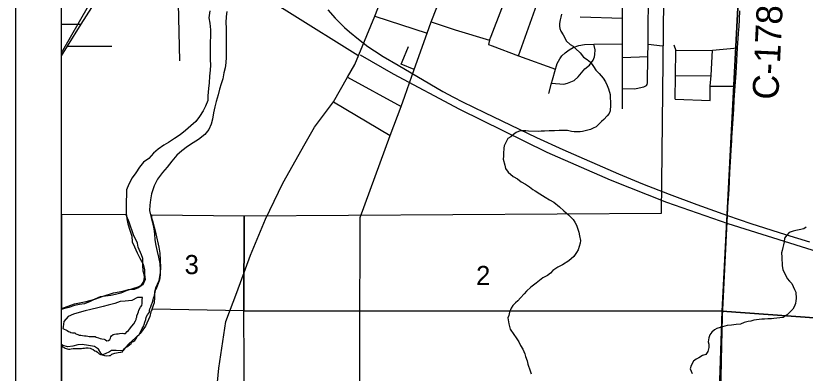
# Model space of a CAD drawing. Extents: x 0 to 34, y 0 to 22.
# Drawn here: x 23.417 to 25.144, y 18.836 to 19.618 of the extents above; entities that cross this region are included whole.
import ezdxf

# ---------------------------------------------------------------- set-up
doc = ezdxf.new("R2010")
doc.units = 0
for name, color, linetype in [('GM_X_City_Street', 7, 'Continuous'), ('GM_X_County_Road', 7, 'Continuous'), ('GM_X_County_Road_Text', 7, 'Continuous'), ('GM_X_Major_River', 7, 'Continuous'), ('GM_X_Minor_River', 7, 'Continuous'), ('GM_X_Rail_Line', 7, 'Continuous'), ('GM_X_Section', 7, 'Continuous'), ('GM_X_Section_Text', 7, 'Continuous'), ('GM_X_Township_Road', 7, 'Continuous'), ('SH_Data', 7, 'Continuous')]:
    doc.layers.add(name, color=color, linetype=linetype)

msp = doc.modelspace()

# ---------------------------------------------------------------- linework, layer by layer
at = {"layer": 'GM_X_City_Street'}
for p, q in [((24.2023, 19.6172), (24.3168, 19.5803)), ((24.652, 19.6161), (24.7447, 19.6129)), ((23.5167, 19.5995), (23.5601, 19.5999)), ((24.4535, 19.5645), (24.4571, 19.5738)), ((23.5301, 19.5518), (23.627, 19.5518)), ((24.8003, 19.5559), (24.832, 19.5522)), ((24.5165, 19.5304), (24.5976, 19.501)), ((24.7446, 19.5266), (24.8, 19.5289)), ((24.1428, 19.4837), (24.2597, 19.4199)), ((24.112, 19.4297), (24.2362, 19.356))]:
    msp.add_line(p, q, dxfattribs=at)
for points in [[(23.9629, 19.1735), (24.0008, 19.2519), (24.0497, 19.3384), (24.0703, 19.3742), (24.112, 19.4297), (24.1428, 19.4837), (24.1587, 19.5115), (24.2023, 19.6172), (24.2092, 19.6341), (24.2339, 19.694), (24.2396, 19.7104), (24.2604, 19.7707), (24.2761, 19.816), (24.2847, 19.8408), (24.2883, 19.8565), (24.2919, 19.8721), (24.2931, 19.8774), (24.3064, 19.9349), (24.3072, 19.9386), (24.3221, 20.0342)], [(24.4571, 19.5738), (24.4804, 19.634), (24.4886, 19.6556), (24.5076, 19.7055), (24.5315, 19.7681), (24.5544, 19.8322), (24.5557, 19.8359), (24.5616, 19.8511), (24.5667, 19.8645), (24.5929, 19.9328)], [(24.7446, 19.4144), (24.7446, 19.4593), (24.7446, 19.5266), (24.7446, 19.557), (24.7445, 19.5967), (24.7447, 19.6129), (24.7452, 19.6848), (24.7455, 19.7113), (24.7457, 19.7375), (24.7462, 19.8063), (24.7462, 19.8086), (24.7615, 19.8472), (24.7705, 19.8699)], [(24.7446, 19.4593), (24.7713, 19.4585), (24.7875, 19.4618), (24.7908, 19.4629), (24.7967, 19.4657), (24.7986, 19.4681), (24.7994, 19.4715), (24.8, 19.5289), (24.8003, 19.5559), (24.8016, 19.6863), (24.802, 19.7187), (24.8027, 19.7879)], [(23.7757, 19.5194), (23.772, 19.6772), (23.7732, 19.7486)], [(24.5832, 19.4484), (24.5892, 19.4709), (24.5911, 19.478), (24.5976, 19.501), (24.5998, 19.5085), (24.6012, 19.5138), (24.607, 19.5238), (24.612, 19.5302), (24.6186, 19.5369), (24.6277, 19.5439), (24.6368, 19.5489), (24.6491, 19.5533), (24.661, 19.5554), (24.6819, 19.5558), (24.7446, 19.557)], [(24.2886, 19.5005), (24.2601, 19.5124), (24.262, 19.517), (24.2763, 19.5511)], [(24.5892, 19.4709), (24.6157, 19.4683), (24.624, 19.4709), (24.6384, 19.4762), (24.6475, 19.4844), (24.6619, 19.5019), (24.672, 19.5097), (24.68, 19.5209), (24.683, 19.5282), (24.6841, 19.5337), (24.6847, 19.5439), (24.6819, 19.5558)]]:
    msp.add_lwpolyline(points, dxfattribs=at)
at = {"layer": 'GM_X_County_Road'}
for p, q in [((24.9977, 19.5686), (24.9984, 19.5788)), ((24.9984, 19.5788), (24.9991, 19.5889)), ((24.9962, 19.5483), (24.997, 19.5585)), ((24.997, 19.5585), (24.9977, 19.5686)), ((24.4594, 19.5522), (24.5165, 19.5304)), ((24.9889, 19.4334), (24.9901, 19.4539)), ((24.9901, 19.4539), (24.9907, 19.4642)), ((24.9877, 19.4129), (24.9889, 19.4334)), ((24.9762, 19.2176), (24.9775, 19.2384))]:
    msp.add_line(p, q, dxfattribs=at)
for points in [[(24.5165, 19.5304), (24.5535, 19.6327), (24.5928, 19.7413), (24.627, 19.8356)], [(24.3256, 19.6051), (24.3523, 19.6717), (24.3553, 19.6792), (24.3743, 19.7264), (24.3832, 19.7487), (24.3849, 19.753), (24.3867, 19.7574), (24.3893, 19.7639)], [(23.5167, 19.5304), (23.5301, 19.5518), (23.5601, 19.5999), (23.5828, 19.6362), (23.5847, 19.6392), (23.6379, 19.6701), (23.6483, 19.6761), (23.7173, 19.7161), (23.7665, 19.7447)], [(24.9991, 19.5889), (24.9994, 19.593), (25.0013, 19.6291)], [(24.1701, 19.1767), (24.2362, 19.356), (24.2597, 19.4199), (24.2678, 19.4419), (24.2886, 19.5005), (24.3168, 19.5803), (24.3256, 19.6051)], [(24.3256, 19.6051), (24.3781, 19.5873), (24.4535, 19.5645), (24.4508, 19.5555), (24.4594, 19.5522)], [(24.9907, 19.4642), (24.9931, 19.4925), (24.9962, 19.5483)], [(24.9851, 19.3717), (24.9865, 19.3924), (24.9877, 19.4129)], [(24.9839, 19.3514), (24.9844, 19.3623), (24.9851, 19.3717)], [(24.9814, 19.3099), (24.9824, 19.3251), (24.9835, 19.3445), (24.9839, 19.3514)], [(24.9775, 19.2384), (24.9792, 19.2756), (24.9814, 19.3099)], [(24.9749, 19.1969), (24.9751, 19.2009), (24.9762, 19.2176)], [(24.9527, 18.4155), (24.9614, 18.8646), (24.963, 18.9602), (24.9739, 19.182), (24.9749, 19.1969)], [(23.7182, 18.4291), (23.7274, 18.4574), (23.7597, 18.5372), (23.7834, 18.6002), (23.8012, 18.6519), (23.8134, 18.6813), (23.8345, 18.7159), (23.8441, 18.7268), (23.8496, 18.7388), (23.8517, 18.7479), (23.8613, 18.8473), (23.8762, 18.9492), (23.9004, 19.0127), (23.9305, 19.0946), (23.9629, 19.1735)]]:
    msp.add_lwpolyline(points, dxfattribs=at)
at = {"layer": 'GM_X_Major_River'}
for points in [[(23.8413, 19.6292), (23.8388, 19.6137), (23.8413, 19.6019), (23.8431, 19.5871), (23.8429, 19.573), (23.842, 19.5609), (23.8419, 19.5488), (23.8421, 19.5362), (23.8423, 19.5226), (23.8426, 19.5104), (23.8417, 19.4994), (23.8408, 19.4858), (23.8395, 19.4713), (23.8382, 19.4592), (23.8373, 19.4433), (23.8368, 19.4327), (23.8321, 19.4206), (23.827, 19.41), (23.8185, 19.3979), (23.8108, 19.387), (23.7997, 19.3773), (23.7882, 19.3671), (23.7763, 19.3574), (23.7641, 19.3495), (23.7511, 19.3409), (23.7404, 19.335), (23.7286, 19.3264), (23.7179, 19.3174), (23.7075, 19.3061), (23.6964, 19.2975), (23.6872, 19.2866), (23.6794, 19.2745), (23.6713, 19.2636), (23.664, 19.2496), (23.6593, 19.2372), (23.6588, 19.2246), (23.6579, 19.214), (23.6581, 19.2003), (23.6583, 19.1863)], [(23.8784, 19.6277), (23.8772, 19.6163), (23.8766, 19.6023), (23.8769, 19.5917), (23.8767, 19.5795), (23.8772, 19.5537), (23.8769, 19.5279), (23.876, 19.5154), (23.8747, 19.504), (23.8723, 19.493), (23.8699, 19.4805), (23.866, 19.4695), (23.8628, 19.4578), (23.8593, 19.4449), (23.8553, 19.4306), (23.8525, 19.4188), (23.8497, 19.4056), (23.8469, 19.3919), (23.8445, 19.3813), (23.8391, 19.3696), (23.8302, 19.3583), (23.8168, 19.3475), (23.805, 19.34), (23.7924, 19.3318), (23.7801, 19.3228), (23.7694, 19.3134), (23.7579, 19.3003), (23.7479, 19.2871), (23.7379, 19.275), (23.7267, 19.2604), (23.7193, 19.246), (23.7138, 19.2286), (23.7114, 19.2157), (23.7097, 19.2036), (23.7092, 19.1922), (23.7128, 19.1766), (23.7161, 19.1659), (23.719, 19.1522), (23.72, 19.1412), (23.721, 19.1283), (23.7231, 19.1154), (23.7264, 19.1021), (23.7293, 19.0903), (23.7318, 19.0762), (23.7324, 19.0621), (23.7327, 19.0515), (23.731, 19.0405), (23.7263, 19.0269), (23.7232, 19.019)], [(23.6583, 19.1863), (23.6597, 19.1741), (23.6622, 19.1631), (23.6666, 19.149), (23.6706, 19.1357), (23.6716, 19.1239), (23.6768, 19.1125), (23.682, 19.0995), (23.6879, 19.0877), (23.6954, 19.0747), (23.6983, 19.0625), (23.6985, 19.0519), (23.6995, 19.0409), (23.6945, 19.0295), (23.6838, 19.0243), (23.672, 19.0207), (23.6583, 19.0166), (23.6465, 19.0111), (23.6351, 19.0081), (23.6244, 19.0064), (23.613, 19.0046), (23.6016, 19.0032), (23.5898, 18.998), (23.5791, 18.9932), (23.5673, 18.988), (23.5563, 18.9862), (23.5453, 18.984), (23.5331, 18.98), (23.5209, 18.9767), (23.5167, 18.9758)], [(23.5167, 18.8959), (23.5196, 18.8937), (23.5222, 18.8921), (23.5249, 18.8913), (23.5294, 18.8893), (23.532, 18.8889), (23.5347, 18.8889), (23.5377, 18.8896), (23.5422, 18.8902), (23.5449, 18.8905), (23.5476, 18.8905), (23.557, 18.8903), (23.5604, 18.8906), (23.5635, 18.8913), (23.5669, 18.8909), (23.5703, 18.8919), (23.5748, 18.8918), (23.5794, 18.891), (23.5827, 18.8898), (23.5857, 18.8882), (23.5899, 18.8855), (23.5925, 18.8843), (23.5955, 18.882), (23.5992, 18.8788), (23.6022, 18.8769), (23.6059, 18.8761), (23.6108, 18.8752), (23.6146, 18.874), (23.621, 18.8746), (23.6241, 18.8753), (23.6268, 18.8775), (23.631, 18.8793), (23.6336, 18.8797), (23.6371, 18.8807), (23.6409, 18.8814), (23.6469, 18.8821), (23.65, 18.8828), (23.652, 18.8869), (23.6528, 18.8895), (23.6566, 18.8921), (23.6612, 18.8947), (23.6659, 18.8991), (23.6689, 18.9014), (23.6709, 18.904), (23.6739, 18.9054), (23.677, 18.9076), (23.679, 18.9103), (23.6805, 18.9129), (23.6821, 18.917), (23.6864, 18.9211), (23.6879, 18.9237), (23.6903, 18.9279), (23.6931, 18.9343), (23.6966, 18.9395), (23.6974, 18.9429), (23.699, 18.9478), (23.7014, 18.9534), (23.7023, 18.9591), (23.705, 18.9636), (23.7074, 18.9666), (23.709, 18.97), (23.7094, 18.9734), (23.7102, 18.9768), (23.7122, 18.9813), (23.7139, 18.9866), (23.7154, 18.9892), (23.7163, 18.9937), (23.7175, 18.9975), (23.7183, 19.0001), (23.7195, 19.0039), (23.7203, 19.0069), (23.722, 19.0137), (23.7232, 19.019)], [(23.5195, 18.934), (23.5291, 18.9296), (23.5317, 18.9276), (23.5347, 18.9264), (23.5373, 18.9256), (23.5407, 18.9248), (23.5456, 18.9243), (23.5482, 18.9223), (23.5524, 18.9207), (23.5553, 18.9192), (23.5588, 18.9195), (23.5629, 18.9186), (23.5671, 18.9182), (23.5708, 18.9177), (23.5742, 18.9169), (23.5772, 18.9165), (23.5814, 18.9164), (23.5875, 18.9166), (23.5901, 18.9166), (23.5927, 18.9154), (23.598, 18.9138), (23.6014, 18.9122), (23.6048, 18.9114), (23.6101, 18.9105), (23.6127, 18.9089), (23.616, 18.907), (23.6195, 18.9076), (23.6222, 18.9103), (23.6237, 18.9129), (23.6245, 18.9155), (23.6261, 18.9181), (23.63, 18.9211), (23.633, 18.9218), (23.6372, 18.9225), (23.6406, 18.922), (23.6436, 18.9231), (23.6493, 18.9237), (23.6531, 18.9229), (23.6565, 18.9232), (23.6604, 18.9273), (23.6631, 18.9295), (23.6654, 18.9329), (23.6709, 18.9392), (23.6751, 18.9441), (23.6787, 18.9505), (23.6799, 18.9535), (23.6803, 18.9561), (23.6819, 18.9588), (23.6819, 18.9614), (23.6839, 18.9671), (23.6855, 18.9708), (23.6863, 18.9738), (23.6899, 18.9806), (23.6922, 18.9843), (23.6935, 18.9885), (23.6936, 18.9968), (23.694, 19.0019)], [(23.694, 19.0019), (23.6828, 19.0016), (23.6709, 18.9952), (23.6557, 18.9935), (23.6451, 18.9932), (23.6337, 18.9888), (23.6189, 18.9848), (23.6082, 18.9822), (23.596, 18.9789), (23.5812, 18.9753), (23.5683, 18.9724), (23.5553, 18.9691), (23.5431, 18.9655), (23.531, 18.9603), (23.5217, 18.9494), (23.5206, 18.9373), (23.5195, 18.934)]]:
    msp.add_lwpolyline(points, dxfattribs=at)
at = {"layer": 'GM_X_Minor_River'}
for points in [[(24.6112, 19.6218), (24.6092, 19.615), (24.608, 19.6093), (24.6068, 19.601), (24.6067, 19.5953), (24.6071, 19.5899), (24.6097, 19.5842), (24.6145, 19.5762), (24.6182, 19.5701), (24.6212, 19.5632), (24.6302, 19.5555), (24.6362, 19.5513), (24.6419, 19.5463), (24.652, 19.5371), (24.6591, 19.5279), (24.6674, 19.5221), (24.6741, 19.5163), (24.6809, 19.5068), (24.6864, 19.4988), (24.6932, 19.4915), (24.7018, 19.4815), (24.707, 19.4735), (24.7111, 19.4655), (24.7137, 19.4582), (24.7173, 19.446), (24.7176, 19.4392), (24.7183, 19.4289)], [(24.7183, 19.4289), (24.7182, 19.4225), (24.7177, 19.41), (24.7153, 19.4043), (24.7107, 19.399), (24.7034, 19.3915), (24.6981, 19.3866), (24.6869, 19.3754), (24.6805, 19.3724), (24.6744, 19.3691), (24.6656, 19.3669), (24.6572, 19.3651), (24.6519, 19.3644), (24.6383, 19.3645), (24.6326, 19.3653), (24.6239, 19.3669), (24.6144, 19.3674), (24.6061, 19.3671), (24.5958, 19.3661), (24.584, 19.3662), (24.5738, 19.366), (24.5666, 19.3657), (24.5609, 19.3653), (24.5385, 19.3656), (24.5325, 19.3664), (24.526, 19.3665), (24.5203, 19.3661), (24.5115, 19.3628), (24.5058, 19.3587), (24.4997, 19.3535), (24.4936, 19.3493), (24.4858, 19.3339), (24.4846, 19.3282), (24.4837, 19.3168), (24.484, 19.3111), (24.4836, 19.3047), (24.4868, 19.291), (24.4886, 19.2837), (24.4939, 19.2757), (24.5051, 19.2665), (24.5149, 19.2614), (24.5228, 19.2549), (24.5323, 19.2495), (24.5409, 19.2437), (24.5481, 19.2383), (24.5533, 19.2348), (24.5635, 19.2283), (24.5752, 19.2213), (24.5846, 19.2155), (24.5944, 19.2101), (24.6064, 19.2001), (24.6162, 19.1916), (24.626, 19.1828), (24.6365, 19.1724), (24.6398, 19.1663), (24.6435, 19.1602), (24.6457, 19.1538), (24.6487, 19.1446), (24.6501, 19.137), (24.6526, 19.1263), (24.6518, 19.121), (24.6471, 19.1063), (24.6436, 19.1003), (24.6382, 19.0916), (24.6271, 19.0818), (24.613, 19.0736), (24.603, 19.068), (24.5919, 19.0606), (24.5869, 19.0549), (24.5801, 19.0501), (24.5698, 19.0449), (24.5556, 19.0332), (24.5441, 19.0243), (24.5342, 19.0156), (24.5295, 19.01), (24.5211, 19.0013), (24.5157, 18.9946), (24.51, 18.9905), (24.5046, 18.9844), (24.5007, 18.9784), (24.4968, 18.9697), (24.4956, 18.9625), (24.4937, 18.9572), (24.4954, 18.9443), (24.4969, 18.9382), (24.4987, 18.9329), (24.5069, 18.9206), (24.5114, 18.9134), (24.5177, 18.905), (24.5214, 18.897), (24.5263, 18.8889), (24.5307, 18.8783), (24.5318, 18.8729), (24.5358, 18.863), (24.5369, 18.8562), (24.5424, 18.8417), (24.5442, 18.8348)], [(25.1465, 19.156), (25.1411, 19.1519), (25.1308, 19.1497), (25.1236, 19.1487), (25.1179, 19.1472), (25.1092, 19.1442), (25.1038, 19.1382), (25.0992, 19.1314), (25.0979, 19.1235), (25.0971, 19.1167), (25.0955, 19.111), (25.0939, 19.1046), (25.0927, 19.0993), (25.093, 19.0901), (25.0939, 19.0708), (25.095, 19.0628), (25.0979, 19.0567), (25.1013, 19.0513), (25.1046, 19.0433), (25.1102, 19.0376), (25.1147, 19.0322), (25.1177, 19.0261), (25.1206, 19.0196), (25.124, 19.0135), (25.1246, 18.9998), (25.1241, 18.9942), (25.1233, 18.9885), (25.1198, 18.9813), (25.1175, 18.976), (25.1102, 18.9692), (25.1045, 18.964), (25.0957, 18.9584), (25.0884, 18.957), (25.082, 18.9566), (25.0755, 18.9556), (25.0702, 18.9553), (25.0626, 18.955), (25.055, 18.9543), (25.049, 18.9543), (25.038, 18.9533), (25.0319, 18.9522), (25.0254, 18.9504), (25.0193, 18.9493), (25.0106, 18.9468), (25.0026, 18.9438), (24.9934, 18.9424), (24.9881, 18.9417), (24.9828, 18.9414), (24.9737, 18.9407), (24.963, 18.9374), (24.9512, 18.9337), (24.9459, 18.9308), (24.9398, 18.9259), (24.9355, 18.9202), (24.9332, 18.9134), (24.9319, 18.9051), (24.9334, 18.8998), (24.9333, 18.8926), (24.9309, 18.8835), (24.9271, 18.8774), (24.9198, 18.8749), (24.9111, 18.87), (24.9053, 18.867), (24.8996, 18.8626), (24.8949, 18.8531), (24.8926, 18.8459), (24.8944, 18.8406), (24.8966, 18.8353)]]:
    msp.add_lwpolyline(points, dxfattribs=at)
at = {"layer": 'GM_X_Rail_Line'}
for points in [[(23.5167, 19.5369), (23.5755, 19.6396), (23.7709, 19.7552), (23.78, 19.7658)], [(23.78, 19.7658), (23.844, 19.7327), (24.0157, 19.6254), (24.1655, 19.5322)], [(24.0992, 19.631), (24.1158, 19.6129), (24.1362, 19.5928), (24.147, 19.5831), (24.1667, 19.5666), (24.1874, 19.5511), (24.2015, 19.5413), (24.2207, 19.5293), (24.2533, 19.5097), (24.3513, 19.4523), (24.3749, 19.4399), (24.3939, 19.4302), (24.4421, 19.4062), (24.5564, 19.3517), (24.6135, 19.3253), (24.736, 19.2722), (24.7881, 19.2508), (24.8462, 19.228), (24.9074, 19.205), (24.9742, 19.181), (25.025, 19.1639), (25.1011, 19.1396), (25.1536, 19.1235)], [(24.1704, 19.5327), (24.2425, 19.4909), (24.3878, 19.4135), (24.5787, 19.3195), (24.7175, 19.2589), (24.8405, 19.2105), (24.9746, 19.1639), (25.4423, 19.0168), (26.3104, 18.7542), (27.1506, 18.4971), (27.9899, 18.2401), (28.4862, 18.088)]]:
    msp.add_lwpolyline(points, dxfattribs=at)
at = {"layer": 'GM_X_Section'}
for points in [[(25.0077, 19.8483), (24.9624, 18.9716), (23.916, 18.9723), (23.9162, 19.1808), (24.83, 19.1865), (24.8367, 19.8516)], [(25.0077, 19.8483), (25.0925, 19.8455), (26.0975, 19.8234), (26.0616, 18.9227), (26.0607, 18.8928), (24.9624, 18.9716)], [(23.5167, 19.1834), (23.5167, 18.9777), (23.5234, 18.9801), (23.5455, 18.9883), (23.5705, 18.9934), (23.5895, 18.9982), (23.5998, 19.0019), (23.6077, 19.0049), (23.6305, 19.012), (23.6506, 19.0157), (23.6635, 19.019), (23.6764, 19.0204), (23.684, 19.0227), (23.6913, 19.0283), (23.697, 19.0366), (23.6986, 19.0461), (23.6975, 19.0521), (23.6952, 19.0593), (23.695, 19.073), (23.6947, 19.0874), (23.6921, 19.095), (23.6846, 19.1121), (23.6831, 19.1204), (23.6745, 19.1391), (23.6648, 19.1668), (23.6581, 19.1828)], [(23.9162, 19.1808), (23.916, 18.9723), (23.7148, 18.9762), (23.7183, 18.9853), (23.7202, 18.991), (23.7207, 19.002), (23.7211, 19.0133), (23.7234, 19.0228), (23.7304, 19.0387), (23.7335, 19.0557), (23.7343, 19.0678), (23.7326, 19.0985), (23.7308, 19.1122), (23.7242, 19.141), (23.7168, 19.1687), (23.7145, 19.1752), (23.7142, 19.1828)], [(24.9624, 18.9716), (24.9267, 17.9117), (23.9224, 17.9096), (23.916, 18.9723)], [(26.0607, 18.8928), (26.0171, 17.9156), (26.0158, 17.891), (24.9267, 17.9117), (24.9624, 18.9716)]]:
    msp.add_lwpolyline(points, close=True, dxfattribs=at)
msp.add_lwpolyline([(23.9224, 17.9096), (23.916, 18.9723), (23.7148, 18.9762), (23.7129, 18.9724), (23.7125, 18.9702), (23.7098, 18.96), (23.7002, 18.9388), (23.6891, 18.9233), (23.6784, 18.9135), (23.6643, 18.9007), (23.6563, 18.8917), (23.6517, 18.8857), (23.6453, 18.8849), (23.6362, 18.8858), (23.626, 18.8858), (23.6214, 18.8832), (23.6126, 18.8783), (23.6062, 18.8765), (23.6028, 18.8803), (23.5975, 18.889), (23.5892, 18.8944), (23.5756, 18.8971), (23.562, 18.8991), (23.5525, 18.898), (23.5415, 18.8954), (23.5309, 18.894), (23.5195, 18.8967), (23.5167, 18.899), (23.5167, 17.9073)], dxfattribs=at)
at = {"layer": 'GM_X_Township_Road'}
for p, q in [((24.8602, 19.4867), (24.9384, 19.4874)), ((24.9364, 19.4641), (24.9907, 19.4642)), ((24.8599, 19.4354), (24.9359, 19.4327))]:
    msp.add_line(p, q, dxfattribs=at)
for points in [[(24.8567, 19.5546), (24.861, 19.5419), (24.9416, 19.5427), (24.9962, 19.5483)], [(24.8599, 19.4354), (24.8602, 19.4867), (24.861, 19.5419)], [(24.9359, 19.4327), (24.9364, 19.4641), (24.9384, 19.4874), (24.9416, 19.5427)], [(24.1778, 18.4409), (24.1684, 18.5138), (24.1687, 18.6361), (24.1687, 18.6441), (24.1694, 18.9087), (24.1701, 19.1767)]]:
    msp.add_lwpolyline(points, dxfattribs=at)
at = {"layer": 'SH_Data'}
for points in [[(23.4167, 21), (30.4167, 21), (30.4167, 14), (23.4167, 14)], [(23.5167, 20.9), (30.3167, 20.9), (30.3167, 14.1), (23.5167, 14.1)]]:
    msp.add_lwpolyline(points, close=True, dxfattribs=at)

# ---------------------------------------------------------------- texts
at = {"layer": 'GM_X_County_Road_Text'}
msp.add_text('C-178', height=0.05682, rotation=87.2485, dxfattribs=at).set_placement((25.0852, 19.4335))
at = {"layer": 'GM_X_Section_Text'}
for s, p in [('3', (23.7861, 19.0529)), ('2', (24.424, 19.029))]:
    msp.add_text(s, height=0.0419, rotation=0, dxfattribs=at).set_placement(p)

doc.saveas('drawing.dxf')
